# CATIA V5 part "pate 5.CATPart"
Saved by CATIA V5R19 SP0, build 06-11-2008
Part number: Part4
Bounding box of the stored display mesh (mm): x -20 to 20, y 0 to 60, z -61.8 to 19.994
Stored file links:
  F:\554\pate 5.CATPart
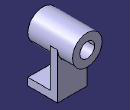
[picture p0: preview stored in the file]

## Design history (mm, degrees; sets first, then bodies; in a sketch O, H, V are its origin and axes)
Body1 (main body)
  Sketch1 on yz-plane, origin (0, 0, 0), H (0, 1, 0), V (0, 0, 1)
    line L1 (0, 0) -> (40, 0)
    line L2 (40, 0) -> (40, -61.8)
    line L3 (40, -61.8) -> (0, -61.8)
    line L4 (0, -61.8) -> (0, 0)
    length L2 = 61.8
    length L3 = 40
    horizontal: L1 H, L3 H
    vertical: L2 V, L4 V
  Pad1: profile Sketch1, direction (1, 0, 0), length 20, mirrored extent
  Sketch2 on end face of Pad1, origin (20, 0, 0), H (0, 1, 0), V (0, 0, 1)
    point P1 (30, 0)
    line L1 (30, 0) -> (30, -51.8)
    line L2 (30, -51.8) -> (0, -51.8)
    point P3 (0, -51.8)
    line L3 (0, -51.8) -> (0, 0)
    line L4 (0, 0) -> (30, 0)
    reference projected line E1 (40, -61.8) -> (40, 0) from edge [face of Pad1 from Sketch1.L2 | end face of Pad1]
    reference projected line E2 (0, -61.8) -> (70.6542, -61.8) from edge [face of Pad1 from Sketch1.L3 | end face of Pad1]
    distance L1 E1 = 10
    distance L2 E2 = 10
    coincidence: P1 H, P3 V
    vertical: L1 V, L3 V
    horizontal: L2 H, L4 H
  Pocket1: profile Sketch2, direction (-1, 0, 0), through (limit type 3)
  Sketch3 on face of Pad1 from Sketch1.L1, origin (0, 0, 0), H (1, 0, 0), V (0, 1, 0)
    line L1 (-20, 60) -> (0, 60)
    line L2 (0, 60) -> (0, 0)
    line L3 (0, 0) -> (-20, 0)
    line L4 (-20, 0) -> (-20, 60)
    point P3 (0, 0)
    reference projected line E1 (20, 30) -> (-20, 30) from edge [face of Pad1 from Sketch1.L1 | face of Pocket1 from Sketch2.L1]
    length L3 = 20
    length L4 = 60
    horizontal: L1 H, L3 H
    vertical: L2 V, L4 V
    coincidence: P3 V
    symmetry: L1 L3 E1
  Shaft1: profile Sketch3, axis Sketch3.L2, angle 360
  Sketch4 on face of Shaft1 from Sketch3.L3, origin (0, 0, 0), H (1, 0, 0), V (0, 0, 1)
    circle A1 centre (0, 0) radius 10
    radius A1 = 10
  Pocket2: profile Sketch4, direction (0, 1, 0), through (limit type 3)
  Point1: type Center, Curve edge [face of Shaft1 from Sketch3.L3 | face of Pocket2 from Sketch4.A1]
  Line1: type Normal, RefSkin face of Shaft1 from Sketch3.L3, Start 0, End 20, RefPoint Point1
  Sketch5 on face of Pad1 from Sketch1.L3, origin (0, 0, -61.8), H (1, 0, 0), V (0, -1, 0)
    circle A1 centre (0, -19.8995) radius 5
    point P1 (0, -19.8995)
    radius A1 = 5
    coincidence: P1 V
  Pocket3: profile Sketch5, direction (0, 0, 1), length 20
